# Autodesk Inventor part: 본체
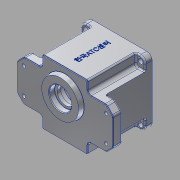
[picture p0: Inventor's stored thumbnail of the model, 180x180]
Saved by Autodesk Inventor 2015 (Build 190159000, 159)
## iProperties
Created: 2016-02
Part Number: 본체
Material: Aluminum 6061
Document SubType Name: Modeling
Designer: Administrator
Mass: 874.257 g
Surface Area: 763.248 cm^2
Volume: 323.799 cm^3
Density: 2.7 g/cm^3
Appearance: Aluminum - Flat
Author: Administrator
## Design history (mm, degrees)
sketch "Sketch1"
  geometry: L1 (70, 30)-(-70, 30); L2 (-70, 30)-(-70, -30); L3 (-70, -30)-(70, -30); L4 (70, -30)-(70, 30); L5 (70, 30)-(-70, -30); L6 (-70, 30)-(70, -30); 1 further point
  constraints: 12 end point, 2 midpoint, 2 parallel, 1 horizontal, 1 perpendicular
  dimensions: "d0" = 140 distance of L3.end L2.end; "d1" = 60 distance of L2.end L1.end
extrude "Extrusion1" new body sketch "Sketch1" distance "d2" = 13; taper "d3" = 0 deg
sketch "Sketch2"
  geometry: L1 (-47, 47)-(47, 47); L2 (47, 47)-(47, -47); L3 (47, -47)-(-47, -47); L4 (-47, -47)-(-47, 47); L5 (-47, 47)-(47, -47); L6 (47, 47)-(-47, -47); 1 further point
  constraints: 12 end point, 2 midpoint, 2 parallel, 1 horizontal, 1 perpendicular
  dimensions: "d4" = 94 distance of L2.end L3.end; "d5" = 94 distance of L1.end L2.end
extrude "Extrusion2" join sketch "Sketch2" distance "d6" = 80; taper "d7" = 0 deg
sketch "Sketch3"
  geometry: C1 r 43 at (0, 0); 1 further point
  constraints: 1 centre point, 1 coincident
  dimensions: "d8" = 86 diameter of C1
extrude "Extrusion3" cut sketch "Sketch3" distance "d9" = 9; taper "d10" = 0 deg
sketch "Sketch4"
  geometry: A1 r 40 centre (0, 0) between (-39.148, 8.214) and (-39.148, -8.214); A2 r 36 centre (0, 0) between (36, 0) and (-36, 0); A3 r 4 centre (36, 0) between (35.854, 3.997) and (35.852, -3.997); A4 r 4 centre (-36, 0) between (-35.852, -3.997) and (-35.852, 3.997); A5 r 3.5 centre (35.722, -7.495) between (39.148, -8.214) and (35.852, -3.997); A6 r 3.5 centre (-35.722, -7.495) between (-35.852, -3.997) and (-39.148, -8.214); A7 r 3.5 centre (-35.722, 7.495) between (-39.148, 8.214) and (-35.852, 3.997); A8 r 3.5 centre (35.722, 7.495) between (35.852, 3.997) and (39.148, 8.214); 1 further point
  constraints: 19 point on circle, 8 centre point, 8 tangent, 4 equal radius, 2 coincident, 2 horizontal alignment
  dimensions: "d11" = 80 diameter of A1; "d12" = 72 diameter of A2; "d13" = 4 radius of A3; "d14" = 3.5 radius of A5
extrude "Extrusion4" cut sketch "Sketch4" distance "d15" = 62; taper "d16" = 0 deg
sketch "Sketch5"
  geometry: C1 r 21 at (0, -11); C2 r 15 at (0, 20); 1 further point
  constraints: 2 centre point, 2 vertical alignment
  dimensions: "d17" = 42 diameter of C1; "d18" = 30 diameter of C2; "d19" = 11 distance of C1.centre point (0, 0); "d20" = 20 distance of point (0, 0) C2.centre
extrude "Extrusion5" join sketch "Sketch5" distance "d21" = 7; taper "d22" = 0 deg
hole "Hole1" diameter "d25" = 25; stored, may be unused: countersink angle "d29" = 90 deg, drill point angle "d31" = 0 deg; dims "d26" = 6, "d27" = 35, "d28" = 10, "d30" = 15, "d118" = 10, "d119" = 10
sketch "Sketch6"
  geometry: C1 r 28 at (0, 11); 1 further point
  constraints: 1 centre point, 1 vertical alignment
  dimensions: "d32" = 56 diameter of C1; "d33" = 11 distance of C1.centre point (0, 0)
extrude "Extrusion6" join sketch "Sketch6" distance "d34" = 7; taper "d35" = -10 deg
hole "Hole2" diameter "d38" = 25; stored, may be unused: countersink angle "d42" = 90 deg, drill point angle "d44" = 0 deg; dims "d36" = 10, "d37" = 10, "d39" = 6, "d40" = 32, "d41" = 8, "d43" = 13
hole "Hole3" diameter "d47" = 19; stored, may be unused: countersink angle "d51" = 90 deg, drill point angle "d53" = 0 deg; dims "d45" = 10, "d46" = 10, "d48" = 6, "d49" = 22, "d50" = 7, "d52" = 8
chamfer "Chamfer1" distance "d54" = 10; stored, may be unused: second distance "d55" = 2, angle "d56" = 45 deg
sketch "Sketch8"
  geometry: 3 further points
  constraints: 1 vertical alignment
  dimensions: "d57" = 38 distance of point (-60, -19) point (-60, 19); "d58" = 19 vertical distance of point (-60, -19) point (0, 0); "d59" = 60 horizontal distance of point (0, 0) point (-60, 19)
hole "Hole4" sketch "Sketch8" at (-60, 19), (-60, -19) diameter "d60" = 5; stored, may be unused: countersink angle "d64" = 90 deg, drill point angle "d66" = 0 deg; dims "d61" = 6, "d62" = 22, "d63" = 7, "d65" = 9
sketch "Sketch9"
  geometry: C1 r 2.5 at (-60, -19) reference; C2 r 2.5 at (-60, 19) reference; 1 further point
hole "Hole5" sketch "Sketch9" at (-60, -19), (-60, 19) diameter "d67" = 9; stored, may be unused: countersink angle "d71" = 90 deg, drill point angle "d73" = 0 deg; dims "d68" = 6, "d69" = 22, "d70" = 7, "d72" = 4
mirror "Mirror1"
sketch "Sketch10"
  geometry: L1 (-47, 47)-(47, 47) reference; L2 (47, 47)-(47, 30) reference; L3 (33, 47)-(47, 47); L4 (47, 47)-(47, 30); L5 (47, 30)-(33, 30); L6 (33, 30)-(33, 47); L7 (33, 47)-(47, 30); L8 (47, 47)-(33, 30); 2 further points
  constraints: 12 end point, 2 midpoint, 2 parallel, 1 horizontal, 1 perpendicular
  dimensions: "d74" = 14 distance of L4.end L5.end; "d75" = 17 distance of L1.end L4.end
extrude "Extrusion7" cut sketch "Sketch10" distance "d76" = 70; taper "d77" = 0 deg
mirror "Mirror2"
mirror "Mirror3"
fillet "Fillet1" dims "d78" = 8
sketch "Sketch12"
  geometry: 3 further points
  constraints: 1 horizontal alignment
  dimensions: "d79" = 40 horizontal distance of point (-33, 30) point (7, 70); "d80" = 80 distance of point (7, 70) point (-73, 70); "d81" = 40 horizontal distance of point (7, 70) point (-33, 30)
hole "Hole6" sketch "Sketch12" at (-73, 70), (7, 70) diameter "d82" = 7; stored, may be unused: countersink angle "d86" = 90 deg, drill point angle "d88" = 0 deg; dims "d83" = 6, "d84" = 22, "d85" = 7, "d87" = 4
mirror "Mirror4"
sketch "Sketch13"
  geometry: A1 r 4 centre (36, 0) between (35.852, 3.997) and (35.852, -3.997) reference; A2 r 4 centre (-36, 0) between (-35.852, -3.997) and (-35.852, 3.997) reference; 1 further point
hole "Hole7" sketch "Sketch13" at (36, 0), (-36, 0) diameter "d89" = 3.242; stored, may be unused: countersink angle "d93" = 90 deg, drill point angle "d95" = 118 deg; dims "d90" = 7, "d91" = 22, "d92" = 7, "d94" = 9
fillet "Fillet2" dims "d97" = 5
sketch "Sketch16" dims "d9" = 9, "d10" = 0
  geometry: L1 (-66, 0)-(0, 0) reference; L2 (-72, 80)-(6, 80) reference; 3 further points
  constraints: 1 midpoint, 1 vertical alignment, 1 other
  dimensions: "d98" = 40 distance from line of L2 point (-33, 40)
emboss "Emboss1" sketch "Sketch16" dims "d9" = 9, "d10" = 0, "d99" = 0.5, "d100" = 0
chamfer "Chamfer2" distance "d101" = 1; stored, may be unused: second distance "d102" = 2, angle "d103" = 45 deg
fillet "Fillet3" dims "d104" = 0.3
fillet "Fillet4" dims "d105" = 5
fillet "Fillet6" dims "d107" = 3
fillet "Fillet7" dims "d108" = 2
fillet "Fillet8" dims "d109" = 2
fillet "Fillet9" dims "d110" = 2
sketch "Sketch17"
  geometry: L1 (-33, 47)-(-33, 35) reference; L2 (-57.929, 30)-(-38, 30) reference; L3 (-68.536, 21.464)-(-61.464, 28.536) reference; L4 (-70, -17.929)-(-70, 17.929) reference; L5 (-61.464, -28.536)-(-68.536, -21.464) reference; L6 (-38, -30)-(-57.929, -30) reference; L7 (-33, -35)-(-33, -47) reference; L8 (33, -47)-(-33, -47) reference; L9 (33, -47)-(33, -35) reference; L10 (57.929, -30)-(38, -30) reference; L11 (68.536, -21.464)-(61.464, -28.536) reference; L12 (70, 17.929)-(70, -17.929) reference; L13 (61.464, 28.536)-(68.536, 21.464) reference; L14 (38, 30)-(57.929, 30) reference; L15 (33, 35)-(33, 47) reference; L16 (-33, 47)-(33, 47) reference; L17 (32, 45)-(32, 35); L18 (38, 29)-(57.929, 29); L19 (60.757, 27.828)-(67.828, 20.757); L20 (69, 17.929)-(69, -17.929); L21 (67.828, -20.757)-(60.757, -27.828); L22 (57.929, -29)-(38, -29); L23 (32, -35)-(32, -45); L24 (31, -46)-(-31, -46); L25 (-32, -45)-(-32, -35); L26 (-38, -29)-(-57.929, -29); L27 (-60.757, -27.828)-(-67.828, -20.757); L28 (-69, -17.929)-(-69, 17.929); L29 (-67.828, 20.757)-(-60.757, 27.828); L30 (-57.929, 29)-(-38, 29); L31 (-32, 35)-(-32, 45); L32 (-31, 46)-(31, 46); C1 r 2.5 at (-60, -19) reference; C2 r 2.5 at (-60, 19) reference; C3 r 2.5 at (60, 19) reference; C4 r 2.5 at (60, -19) reference; A1 r 5 centre (-38, 35) between (-38, 30) and (-33, 35) reference; A2 r 5 centre (-57.929, 25) between (-57.929, 30) and (-61.464, 28.536) reference; A3 r 5 centre (-65, 17.929) between (-68.536, 21.464) and (-70, 17.929) reference; A4 r 5 centre (-65, -17.929) between (-70, -17.929) and (-68.536, -21.464) reference; A5 r 5 centre (-57.929, -25) between (-61.464, -28.536) and (-57.929, -30) reference; A6 r 5 centre (-38, -35) between (-33, -35) and (-38, -30) reference; A7 r 5 centre (38, -35) between (38, -30) and (33, -35) reference; A8 r 5 centre (57.929, -25) between (57.929, -30) and (61.464, -28.536) reference; A9 r 5 centre (65, -17.929) between (68.536, -21.464) and (70, -17.929) reference; A10 r 5 centre (65, 17.929) between (70, 17.929) and (68.536, 21.464) reference; A11 r 5 centre (57.929, 25) between (61.464, 28.536) and (57.929, 30) reference; A12 r 5 centre (38, 35) between (33, 35) and (38, 30) reference; A13 r 1 centre (31, 45) between (32, 45) and (31, 46); A14 r 6 centre (38, 35) between (32, 35) and (38, 29); A15 r 4 centre (57.929, 25) between (60.757, 27.828) and (57.929, 29); A16 r 4 centre (65, 17.929) between (69, 17.929) and (67.828, 20.757); A17 r 4 centre (65, -17.929) between (67.828, -20.757) and (69, -17.929); A18 r 4 centre (57.929, -25) between (57.929, -29) and (60.757, -27.828); A19 r 6 centre (38, -35) between (38, -29) and (32, -35); A20 r 1 centre (31, -45) between (31, -46) and (32, -45); A21 r 1 centre (-31, -45) between (-32, -45) and (-31, -46); A22 r 6 centre (-38, -35) between (-32, -35) and (-38, -29); A23 r 4 centre (-57.929, -25) between (-60.757, -27.828) and (-57.929, -29); A24 r 4 centre (-65, -17.929) between (-69, -17.929) and (-67.828, -20.757); A25 r 4 centre (-65, 17.929) between (-67.828, 20.757) and (-69, 17.929); A26 r 4 centre (-57.929, 25) between (-57.929, 29) and (-60.757, 27.828); A27 r 6 centre (-38, 35) between (-38, 29) and (-32, 35); A28 r 1 centre (-31, 45) between (-31, 46) and (-32, 45); 1 further point
  constraints: 32 end point, 32 point on circle, 16 centre point, 24 other
  dimensions: "d111" = 1 distance between parallel lines of L16 L32
extrude "Extrusion8" cut sketch "Sketch17" distance "d112" = 1; taper "d113" = 0 deg
fillet "Fillet10" dims "d114" = 2
fillet "Fillet11" dims "d115" = 0.3
fillet "Fillet12" dims "d116" = 2
fillet "Fillet13" dims "d117" = 2
body "Solid1"
node "Projected Loop2"
